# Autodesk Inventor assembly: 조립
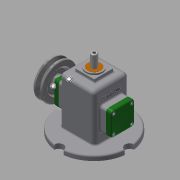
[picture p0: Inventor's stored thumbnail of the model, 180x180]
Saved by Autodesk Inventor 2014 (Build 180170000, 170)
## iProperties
Created: 2018-07
Part Number: 조립
Document SubType Name: Assembly
Designer: kh
Author: kh
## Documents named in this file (16)
- C:\Users\kh\Desktop\480707V1018\조립.iam
- C:\Users\kh\Desktop\480707V1018\본체.ipt
- C:\Users\kh\Desktop\480707V1018\V벨트풀리.ipt
- C:\Users\kh\Desktop\480707V1018\고정핀 1.2x8.ipt
- C:\Users\kh\Desktop\480707V1018\뒤커버.ipt
- C:\Users\kh\Desktop\480707V1018\링크.ipt
- C:\Users\kh\Desktop\480707V1018\멈춤나사 M3x8.ipt
- C:\Users\kh\Desktop\480707V1018\베어링 12x32x10.ipt
- C:\Users\kh\Desktop\480707V1018\볼트 M4.ipt
- C:\Users\kh\Desktop\480707V1018\부시.ipt
- C:\Users\kh\Desktop\480707V1018\슬라이드.ipt
- C:\Users\kh\Desktop\480707V1018\앞커버.ipt
- C:\Users\kh\Desktop\480707V1018\오일 실 12 25 7.ipt
- C:\Users\kh\Desktop\480707V1018\키 4x4x10.ipt
- C:\Users\kh\Desktop\480707V1018\편심축.ipt
- C:\Users\kh\Desktop\480707V1018\핀 5x18.ipt
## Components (3 placed, 3 different names)
1. V벨트풀리:1 — Mate:15, Mate:16, Flush:2
2. 고정핀 1.2x8:1 — Mate:5
3. 핀 5x18:1 — Insert:3, Mate:5
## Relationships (5: Mate 3, Insert 1, Flush 1)
- Insert:3: 핀 5x18:1
- Mate:5: 고정핀 1.2x8:1 ↔ 핀 5x18:1
- Mate:15: V벨트풀리:1
- Mate:16: V벨트풀리:1
- Flush:2: V벨트풀리:1
